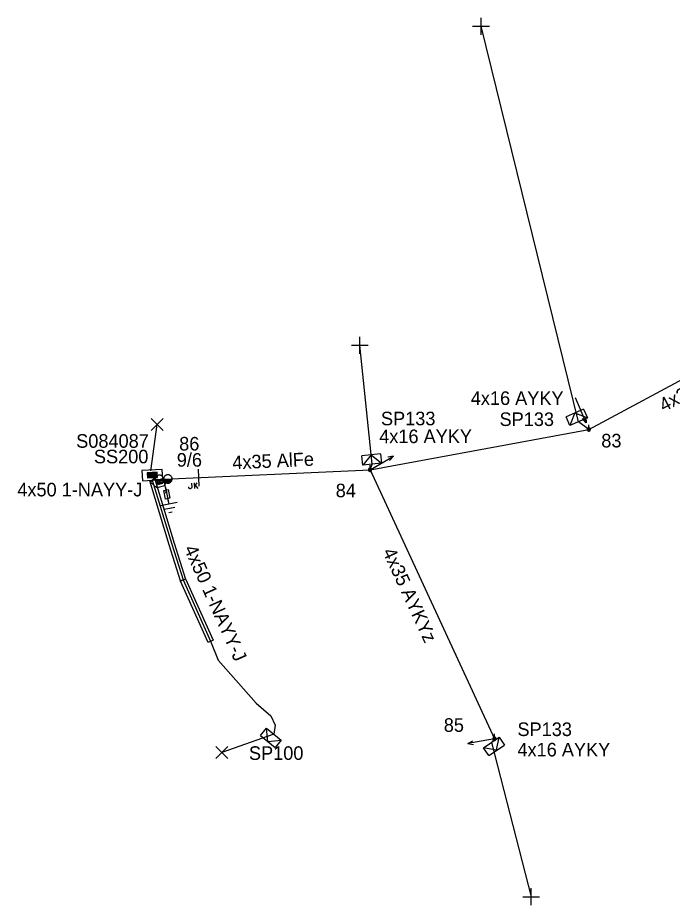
# Model space of a CAD drawing. Extents: x -788458 to -786145, y -1154772 to -1152372.
# Drawn here: x -787276.6 to -787228.3, y -1152553.9 to -1152488.5 of the extents above; entities that cross this region are included whole.
import ezdxf

# ---------------------------------------------------------------- set-up
doc = ezdxf.new("R2010")
doc.units = 0
for name, color, linetype in [('Vrstva 1', 7, 'Continuous'), ('Vrstva 12', 7, 'Continuous'), ('Vrstva 13', 7, 'Continuous'), ('Vrstva 14', 7, 'Continuous'), ('Vrstva 15', 7, 'Continuous'), ('Vrstva 16', 7, 'Continuous'), ('Vrstva 18', 7, 'Continuous'), ('Vrstva 2', 7, 'Continuous'), ('Vrstva 20', 7, 'Continuous'), ('Vrstva 28', 7, 'Continuous'), ('Vrstva 29', 7, 'Continuous'), ('Vrstva 30', 7, 'Continuous'), ('Vrstva 31', 7, 'Continuous'), ('Vrstva 33', 7, 'Continuous'), ('Vrstva 34', 7, 'Continuous'), ('Vrstva 5', 7, 'Continuous'), ('Vrstva 52', 7, 'Continuous'), ('Vrstva 53', 7, 'Continuous'), ('Vrstva 54', 7, 'Continuous'), ('Vrstva 59', 7, 'Continuous'), ('Vrstva 6', 7, 'Continuous'), ('Vrstva 8', 7, 'Continuous'), ('Vrstva 9', 7, 'Continuous')]:
    doc.layers.add(name, color=color, linetype=linetype)

# ---------------------------------------------------------------- blocks, each defined once
blk = doc.blocks.new('NN450')
at = {"layer": 'Vrstva 2'}
for points in [[(0, 0), (0, 0.07), (-0.01, 0.13), (-0.03, 0.19), (-0.05, 0.25), (-0.08, 0.31), (-0.12, 0.37), (-0.16, 0.42), (-0.21, 0.46), (-0.26, 0.51), (-0.31, 0.54), (-0.37, 0.57), (-0.43, 0.59), (-0.5, 0.61), (-0.56, 0.62), (-0.63, 0.62), (-0.69, 0.62), (-0.75, 0.61), (-0.82, 0.59), (-0.88, 0.57), (-0.94, 0.54), (-0.99, 0.51), (-1.04, 0.46), (-1.09, 0.42), (-1.13, 0.37), (-1.17, 0.31), (-1.2, 0.25), (-1.22, 0.19), (-1.24, 0.13), (-1.25, 0.07), (-1.25, 0), (-1.25, -0.07), (-1.24, -0.13), (-1.22, -0.19), (-1.2, -0.25), (-1.17, -0.31), (-1.13, -0.37), (-1.09, -0.42), (-1.04, -0.46), (-0.99, -0.51), (-0.94, -0.54), (-0.88, -0.57), (-0.82, -0.59), (-0.75, -0.61), (-0.69, -0.62), (-0.62, -0.63), (-0.56, -0.62), (-0.5, -0.61), (-0.43, -0.59), (-0.37, -0.57), (-0.31, -0.54), (-0.26, -0.51), (-0.21, -0.46), (-0.16, -0.42), (-0.12, -0.37), (-0.08, -0.31), (-0.05, -0.25), (-0.03, -0.19), (-0.01, -0.13), (0, -0.07), (0, 0)], [(1.25, 0), (1.25, 0.07), (1.24, 0.13), (1.22, 0.19), (1.2, 0.25), (1.17, 0.31), (1.13, 0.37), (1.09, 0.42), (1.04, 0.46), (0.99, 0.51), (0.94, 0.54), (0.88, 0.57), (0.82, 0.59), (0.75, 0.61), (0.69, 0.62), (0.62, 0.62), (0.56, 0.62), (0.5, 0.61), (0.43, 0.59), (0.37, 0.57), (0.31, 0.54), (0.26, 0.51), (0.21, 0.46), (0.16, 0.42), (0.12, 0.37), (0.08, 0.31), (0.05, 0.25), (0.03, 0.19), (0.01, 0.13), (0, 0.07), (0, 0), (0, -0.07), (0.01, -0.13), (0.03, -0.19), (0.05, -0.25), (0.08, -0.31), (0.12, -0.37), (0.16, -0.42), (0.21, -0.46), (0.26, -0.51), (0.31, -0.54), (0.37, -0.57), (0.43, -0.59), (0.5, -0.61), (0.56, -0.62), (0.63, -0.63), (0.69, -0.62), (0.75, -0.61), (0.82, -0.59), (0.88, -0.57), (0.94, -0.54), (0.99, -0.51), (1.04, -0.46), (1.09, -0.42), (1.13, -0.37), (1.17, -0.31), (1.2, -0.25), (1.22, -0.19), (1.24, -0.13), (1.25, -0.07), (1.25, 0)], [(-1.25, 0), (1.25, 0)], [(-1.23, -0.16), (-0.02, -0.16)], [(-1.16, -0.32), (-0.09, -0.32)], [(-1.03, -0.47), (-0.22, -0.47)], [(0.02, -0.16), (1.23, -0.16)], [(0.09, -0.32), (1.16, -0.32)], [(0.22, -0.47), (1.03, -0.47)]]:
    blk.add_lwpolyline(points, dxfattribs=at)
blk = doc.blocks.new('NN560')
at = {"layer": 'Vrstva 2'}
for points in [[(1.999, -0.001), (1.59, 0.141)], [(0, -0.001), (1.999, -0.001)], [(1.999, -0.001), (1.59, -0.134)]]:
    blk.add_lwpolyline(points, dxfattribs=at)
blk = doc.blocks.new('NN840')
at = {"layer": 'Vrstva 15'}
for points in [[(0.003, 0.619), (0.003, -0.631)], [(-0.538, -0.385), (-0.538, -0.71)], [(-0.332, -0.385), (-0.332, -0.798)], [(-0.332, -0.641), (-0.125, -0.385)], [(-0.263, -0.557), (-0.091, -0.798)], [(-0.745, -0.71), (-0.745, -0.66)], [(-0.73, -0.764), (-0.745, -0.71)], [(-0.657, -0.798), (-0.73, -0.764)], [(-0.627, -0.798), (-0.657, -0.798)], [(-0.558, -0.764), (-0.627, -0.798)], [(-0.538, -0.71), (-0.558, -0.764)]]:
    blk.add_lwpolyline(points, dxfattribs=at)
blk = doc.blocks.new('NN565')
at = {"layer": 'Vrstva 2'}
for points in [[(0.015, 0.528), (0.015, 2.528)], [(0.157, 0.937), (0.015, 0.528), (-0.119, 0.937)]]:
    blk.add_lwpolyline(points, dxfattribs=at)
blk = doc.blocks.new('NN800')
at = {"layer": 'Vrstva 1'}
for points in [[(-0.442, 0.442), (0.442, -0.442)], [(-0.442, -0.442), (0.442, 0.442)]]:
    blk.add_lwpolyline(points, dxfattribs=at)
blk = doc.blocks.new('NN820')
at = {"layer": 'Vrstva 13'}
for points in [[(-0.003, 0.004), (-0.003, -1.049)], [(-0.165, -0.813), (0.165, -0.813)], [(-0.165, -1.473), (-0.165, -0.813)], [(-0.003, -1.049), (-0.062, -0.926)], [(-0.003, -1.049), (0.057, -0.926)], [(0.165, -0.813), (0.165, -1.473)], [(0.165, -1.473), (-0.165, -1.473)], [(-0.003, -1.473), (-0.003, -1.871)]]:
    blk.add_lwpolyline(points, dxfattribs=at)
blk = doc.blocks.new('NN620')
at = {"layer": 'Vrstva 8'}
for points in [[(0.752, 0.004), (-0.748, 0.004)], [(-0.748, 0.004), (-0.748, -0.746)], [(0.752, -0.746), (0.752, 0.004)], [(0.368, -0.18), (-0.376, -0.18)], [(-0.376, -0.18), (-0.376, -0.558)], [(-0.376, -0.558), (0.368, -0.558)], [(0.321, -0.227), (-0.329, -0.227)], [(-0.329, -0.227), (-0.329, -0.51)], [(-0.329, -0.51), (0.321, -0.51)], [(0.274, -0.274), (-0.281, -0.274)], [(-0.281, -0.274), (-0.281, -0.463)], [(-0.281, -0.463), (0.274, -0.463)], [(0.227, -0.321), (-0.234, -0.321)], [(-0.234, -0.321), (-0.234, -0.416)], [(-0.234, -0.416), (0.227, -0.416)], [(-0.193, -0.369), (0.185, -0.369)], [(0.227, -0.416), (0.227, -0.321)], [(0.274, -0.463), (0.274, -0.274)], [(0.321, -0.51), (0.321, -0.227)], [(0.368, -0.558), (0.368, -0.18)], [(-0.748, -0.746), (0.752, -0.746)]]:
    blk.add_lwpolyline(points, dxfattribs=at)
blk = doc.blocks.new('NN630')
at = {"layer": 'Vrstva 9'}
for points in [[(-0.003, -0.7), (-0.703, 0)], [(-0.703, -0.7), (-0.703, 0), (0.697, 0), (0.697, -0.7)], [(-0.003, -0.7), (0.697, 0)], [(-0.703, -0.7), (0.697, -0.7)]]:
    blk.add_lwpolyline(points, dxfattribs=at)
blk = doc.blocks.new('NN810')
at = {"layer": 'Vrstva 14'}
for points in [[(0.004, -0.64), (0.004, -1.89)], [(0.629, -1.89), (-0.621, -1.89)], [(0.388, -2.2), (-0.399, -2.2)], [(0.004, -2.515), (-0.124, -2.515)], [(0.137, -2.515), (0.004, -2.515)]]:
    blk.add_lwpolyline(points, dxfattribs=at)
blk = doc.blocks.new('NN500')
at = {"layer": 'Vrstva 2'}
for points in [[(0, -0.24), (0.02, -0.23), (0.05, -0.23), (0.07, -0.22), (0.09, -0.22), (0.12, -0.2), (0.14, -0.19), (0.16, -0.18), (0.17, -0.16), (0.19, -0.14), (0.2, -0.12), (0.21, -0.1), (0.22, -0.07), (0.23, -0.05), (0.23, -0.02), (0.23, 0), (0.23, 0.02), (0.23, 0.05), (0.22, 0.07), (0.21, 0.1), (0.2, 0.12), (0.19, 0.14), (0.17, 0.16), (0.16, 0.17), (0.14, 0.19), (0.12, 0.2), (0.09, 0.21), (0.07, 0.22), (0.05, 0.23), (0.02, 0.23), (0, 0.23), (-0.03, 0.23), (-0.05, 0.23), (-0.07, 0.22), (-0.1, 0.21), (-0.12, 0.2), (-0.14, 0.19), (-0.16, 0.17), (-0.18, 0.16), (-0.19, 0.14), (-0.2, 0.12), (-0.22, 0.1), (-0.22, 0.07), (-0.23, 0.05), (-0.23, 0.02), (-0.24, 0), (-0.23, -0.02), (-0.23, -0.05), (-0.22, -0.07), (-0.22, -0.1), (-0.2, -0.12), (-0.19, -0.14), (-0.18, -0.16), (-0.16, -0.18), (-0.14, -0.19), (-0.12, -0.2), (-0.1, -0.22), (-0.07, -0.22), (-0.05, -0.23), (-0.03, -0.23), (0, -0.24)], [(0, -0.24), (0.02, -0.23), (0.05, -0.23), (0.07, -0.22), (0.09, -0.22), (0.12, -0.2), (0.14, -0.19), (0.16, -0.18), (0.17, -0.16), (0.19, -0.14), (0.2, -0.12), (0.21, -0.1), (0.22, -0.07), (0.23, -0.05), (0.23, -0.02), (0.23, 0), (0.23, 0.02), (0.23, 0.05), (0.22, 0.07), (0.21, 0.1), (0.2, 0.12), (0.19, 0.14), (0.17, 0.16), (0.16, 0.17), (0.14, 0.19), (0.12, 0.2), (0.09, 0.21), (0.07, 0.22), (0.05, 0.23), (0.02, 0.23), (0, 0.23), (-0.03, 0.23), (-0.05, 0.23), (-0.07, 0.22), (-0.1, 0.21), (-0.12, 0.2), (-0.14, 0.19), (-0.16, 0.17), (-0.18, 0.16), (-0.19, 0.14), (-0.2, 0.12), (-0.22, 0.1), (-0.22, 0.07), (-0.23, 0.05), (-0.23, 0.02), (-0.24, 0), (-0.23, -0.02), (-0.23, -0.05), (-0.22, -0.07), (-0.22, -0.1), (-0.2, -0.12), (-0.19, -0.14), (-0.18, -0.16), (-0.16, -0.18), (-0.14, -0.19), (-0.12, -0.2), (-0.1, -0.22), (-0.07, -0.22), (-0.05, -0.23), (-0.03, -0.23), (0, -0.24)], [(0, -0.21), (0.02, -0.2), (0.04, -0.2), (0.06, -0.2), (0.08, -0.19), (0.1, -0.18), (0.12, -0.17), (0.14, -0.15), (0.15, -0.14), (0.16, -0.12), (0.18, -0.1), (0.19, -0.08), (0.19, -0.06), (0.2, -0.04), (0.2, -0.02), (0.2, 0), (0.2, 0.02), (0.2, 0.04), (0.19, 0.06), (0.19, 0.08), (0.18, 0.1), (0.16, 0.12), (0.15, 0.14), (0.14, 0.15), (0.12, 0.17), (0.1, 0.18), (0.08, 0.19), (0.06, 0.19), (0.04, 0.2), (0.02, 0.2), (0, 0.2), (-0.02, 0.2), (-0.04, 0.2), (-0.06, 0.19), (-0.08, 0.19), (-0.1, 0.18), (-0.12, 0.17), (-0.14, 0.15), (-0.15, 0.14), (-0.17, 0.12), (-0.18, 0.1), (-0.19, 0.08), (-0.2, 0.06), (-0.2, 0.04), (-0.21, 0.02), (-0.21, 0), (-0.21, -0.02), (-0.2, -0.04), (-0.2, -0.06), (-0.19, -0.08), (-0.18, -0.1), (-0.17, -0.12), (-0.15, -0.14), (-0.14, -0.15), (-0.12, -0.17), (-0.1, -0.18), (-0.08, -0.19), (-0.06, -0.2), (-0.04, -0.2), (-0.02, -0.2), (0, -0.21)], [(0, -0.18), (0.02, -0.18), (0.04, -0.17), (0.05, -0.17), (0.07, -0.16), (0.09, -0.15), (0.1, -0.14), (0.12, -0.13), (0.13, -0.12), (0.14, -0.1), (0.15, -0.09), (0.16, -0.07), (0.17, -0.05), (0.17, -0.04), (0.17, -0.02), (0.17, 0), (0.17, 0.02), (0.17, 0.04), (0.17, 0.05), (0.16, 0.07), (0.15, 0.09), (0.14, 0.1), (0.13, 0.12), (0.12, 0.13), (0.1, 0.14), (0.09, 0.15), (0.07, 0.16), (0.05, 0.17), (0.04, 0.17), (0.02, 0.17), (0, 0.18), (-0.02, 0.17), (-0.04, 0.17), (-0.06, 0.17), (-0.07, 0.16), (-0.09, 0.15), (-0.1, 0.14), (-0.12, 0.13), (-0.13, 0.12), (-0.14, 0.1), (-0.15, 0.09), (-0.16, 0.07), (-0.17, 0.05), (-0.17, 0.04), (-0.18, 0.02), (-0.18, 0), (-0.18, -0.02), (-0.17, -0.04), (-0.17, -0.05), (-0.16, -0.07), (-0.15, -0.09), (-0.14, -0.1), (-0.13, -0.12), (-0.12, -0.13), (-0.1, -0.14), (-0.09, -0.15), (-0.07, -0.16), (-0.06, -0.17), (-0.04, -0.17), (-0.02, -0.18), (0, -0.18)], [(0, -0.15), (0.01, -0.15), (0.03, -0.14), (0.04, -0.14), (0.06, -0.13), (0.07, -0.13), (0.08, -0.12), (0.1, -0.11), (0.11, -0.1), (0.12, -0.09), (0.13, -0.07), (0.13, -0.06), (0.14, -0.05), (0.14, -0.03), (0.14, -0.02), (0.14, 0), (0.14, 0.01), (0.14, 0.03), (0.14, 0.04), (0.13, 0.06), (0.13, 0.07), (0.12, 0.09), (0.11, 0.1), (0.1, 0.11), (0.08, 0.12), (0.07, 0.13), (0.06, 0.13), (0.04, 0.14), (0.03, 0.14), (0.01, 0.14), (0, 0.15), (-0.02, 0.14), (-0.03, 0.14), (-0.05, 0.14), (-0.06, 0.13), (-0.07, 0.13), (-0.09, 0.12), (-0.1, 0.11), (-0.11, 0.1), (-0.12, 0.09), (-0.13, 0.07), (-0.13, 0.06), (-0.14, 0.04), (-0.14, 0.03), (-0.15, 0.01), (-0.15, 0), (-0.15, -0.02), (-0.14, -0.03), (-0.14, -0.05), (-0.13, -0.06), (-0.13, -0.07), (-0.12, -0.09), (-0.11, -0.1), (-0.1, -0.11), (-0.09, -0.12), (-0.07, -0.13), (-0.06, -0.13), (-0.05, -0.14), (-0.03, -0.14), (-0.02, -0.15), (0, -0.15)], [(0, -0.12), (0.01, -0.12), (0.02, -0.11), (0.03, -0.11), (0.05, -0.11), (0.06, -0.1), (0.07, -0.09), (0.08, -0.09), (0.09, -0.08), (0.09, -0.07), (0.1, -0.06), (0.11, -0.05), (0.11, -0.04), (0.11, -0.02), (0.11, -0.01), (0.12, 0), (0.11, 0.01), (0.11, 0.02), (0.11, 0.04), (0.11, 0.05), (0.1, 0.06), (0.09, 0.07), (0.09, 0.08), (0.08, 0.09), (0.07, 0.09), (0.06, 0.1), (0.05, 0.11), (0.03, 0.11), (0.02, 0.11), (0.01, 0.12), (0, 0.12), (-0.01, 0.12), (-0.03, 0.11), (-0.04, 0.11), (-0.05, 0.11), (-0.06, 0.1), (-0.07, 0.09), (-0.08, 0.09), (-0.09, 0.08), (-0.1, 0.07), (-0.1, 0.06), (-0.11, 0.05), (-0.11, 0.04), (-0.12, 0.02), (-0.12, 0.01), (-0.12, 0), (-0.12, -0.01), (-0.12, -0.02), (-0.11, -0.04), (-0.11, -0.05), (-0.1, -0.06), (-0.1, -0.07), (-0.09, -0.08), (-0.08, -0.09), (-0.07, -0.09), (-0.06, -0.1), (-0.05, -0.11), (-0.04, -0.11), (-0.03, -0.11), (-0.01, -0.12), (0, -0.12)], [(0, -0.09), (0.01, -0.09), (0.02, -0.09), (0.03, -0.08), (0.03, -0.08), (0.04, -0.08), (0.05, -0.07), (0.06, -0.07), (0.06, -0.06), (0.07, -0.05), (0.07, -0.04), (0.08, -0.04), (0.08, -0.03), (0.08, -0.02), (0.09, -0.01), (0.09, 0), (0.09, 0.01), (0.08, 0.02), (0.08, 0.03), (0.08, 0.03), (0.07, 0.04), (0.07, 0.05), (0.06, 0.06), (0.06, 0.06), (0.05, 0.07), (0.04, 0.07), (0.03, 0.08), (0.03, 0.08), (0.02, 0.08), (0.01, 0.09), (0, 0.09), (-0.01, 0.09), (-0.02, 0.08), (-0.03, 0.08), (-0.04, 0.08), (-0.04, 0.07), (-0.05, 0.07), (-0.06, 0.06), (-0.07, 0.06), (-0.07, 0.05), (-0.08, 0.04), (-0.08, 0.03), (-0.08, 0.03), (-0.09, 0.02), (-0.09, 0.01), (-0.09, 0), (-0.09, -0.01), (-0.09, -0.02), (-0.08, -0.03), (-0.08, -0.04), (-0.08, -0.04), (-0.07, -0.05), (-0.07, -0.06), (-0.06, -0.07), (-0.05, -0.07), (-0.04, -0.08), (-0.04, -0.08), (-0.03, -0.08), (-0.02, -0.09), (-0.01, -0.09), (0, -0.09)], [(0, -0.06), (0, -0.06), (0.01, -0.06), (0.02, -0.05), (0.02, -0.05), (0.03, -0.05), (0.03, -0.05), (0.04, -0.04), (0.04, -0.04), (0.05, -0.03), (0.05, -0.03), (0.05, -0.02), (0.05, -0.02), (0.05, -0.01), (0.06, -0.01), (0.06, 0), (0.06, 0.01), (0.05, 0.01), (0.05, 0.02), (0.05, 0.02), (0.05, 0.03), (0.05, 0.03), (0.04, 0.04), (0.04, 0.04), (0.03, 0.05), (0.03, 0.05), (0.02, 0.05), (0.02, 0.05), (0.01, 0.06), (0, 0.06), (0, 0.06), (-0.01, 0.06), (-0.01, 0.06), (-0.02, 0.05), (-0.02, 0.05), (-0.03, 0.05), (-0.03, 0.05), (-0.04, 0.04), (-0.04, 0.04), (-0.05, 0.03), (-0.05, 0.03), (-0.05, 0.02), (-0.06, 0.02), (-0.06, 0.01), (-0.06, 0.01), (-0.06, 0), (-0.06, -0.01), (-0.06, -0.01), (-0.06, -0.02), (-0.05, -0.02), (-0.05, -0.03), (-0.05, -0.03), (-0.04, -0.04), (-0.04, -0.04), (-0.03, -0.05), (-0.03, -0.05), (-0.02, -0.05), (-0.02, -0.05), (-0.01, -0.06), (-0.01, -0.06), (0, -0.06)], [(0, -0.03), (0, -0.03), (0, -0.03), (0.01, -0.03), (0.01, -0.03), (0.01, -0.02), (0.02, -0.02), (0.02, -0.02), (0.02, -0.02), (0.02, -0.02), (0.02, -0.01), (0.02, -0.01), (0.03, -0.01), (0.03, -0.01), (0.03, 0), (0.03, 0), (0.03, 0), (0.03, 0.01), (0.03, 0.01), (0.02, 0.01), (0.02, 0.01), (0.02, 0.02), (0.02, 0.02), (0.02, 0.02), (0.02, 0.02), (0.01, 0.02), (0.01, 0.02), (0.01, 0.03), (0, 0.03), (0, 0.03), (0, 0.03), (0, 0.03), (-0.01, 0.03), (-0.01, 0.03), (-0.01, 0.02), (-0.02, 0.02), (-0.02, 0.02), (-0.02, 0.02), (-0.02, 0.02), (-0.02, 0.02), (-0.03, 0.01), (-0.03, 0.01), (-0.03, 0.01), (-0.03, 0.01), (-0.03, 0), (-0.03, 0), (-0.03, 0), (-0.03, -0.01), (-0.03, -0.01), (-0.03, -0.01), (-0.03, -0.01), (-0.02, -0.02), (-0.02, -0.02), (-0.02, -0.02), (-0.02, -0.02), (-0.02, -0.02), (-0.01, -0.03), (-0.01, -0.03), (-0.01, -0.03), (0, -0.03), (0, -0.03)], [(0.23, 0), (0.7, 0)]]:
    blk.add_lwpolyline(points, dxfattribs=at)

msp = doc.modelspace()

# ---------------------------------------------------------------- linework, layer by layer
at = {"layer": 'Vrstva 1'}
for points in [[(-787250.63, -1152521.8), (-787234.5, -1152518.83), (-787219.59, -1152510.84), (-787199.57, -1152504.09)], [(-787265.84, -1152522.49), (-787250.63, -1152521.8)]]:
    msp.add_lwpolyline(points, dxfattribs=at)
at = {"layer": 'Vrstva 20'}
for points in [[(-787266.489, -1152522.502), (-787265.059, -1152527.211), (-787264.219, -1152529.849), (-787264.601, -1152529.971), (-787265.441, -1152527.329), (-787266.871, -1152522.618)], [(-787266.547, -1152522.411), (-787266.245, -1152522.681), (-787266.091, -1152522.643), (-787266.033, -1152522.436), (-787265.647, -1152522.544), (-787265.769, -1152522.977), (-787266.355, -1152523.119), (-787266.813, -1152522.709)], [(-787264.228, -1152529.828), (-787262.198, -1152534.348), (-787262.562, -1152534.512), (-787264.592, -1152529.992)]]:
    msp.add_lwpolyline(points, close=True, dxfattribs=at)
at = {"layer": 'Vrstva 5'}
for points in [[(-787266.68, -1152522.56), (-787265.25, -1152527.27), (-787264.41, -1152529.91), (-787262.38, -1152534.43), (-787261.83, -1152535.83), (-787259.01, -1152539), (-787257.94, -1152539.92), (-787257.62, -1152540.61), (-787257.71, -1152541.28)], [(-787265.84, -1152522.49), (-787265.93, -1152522.81), (-787266.3, -1152522.9), (-787266.459, -1152522.546)]]:
    msp.add_lwpolyline(points, dxfattribs=at)
at = {"layer": 'Vrstva 52'}
for points in [[(-787234.5, -1152518.83), (-787235.25, -1152518.26)], [(-787250.63, -1152521.8), (-787250.47, -1152521.39)], [(-787250.63, -1152521.8), (-787241.46, -1152541.61)], [(-787241.46, -1152541.61), (-787241.68, -1152541.88)]]:
    msp.add_lwpolyline(points, dxfattribs=at)
at = {"layer": 'Vrstva 59'}
for points in [[(-787235.25, -1152518.26), (-787242.44, -1152489.13)], [(-787250.47, -1152521.39), (-787251.38, -1152512.63)], [(-787266.791, -1152521.884), (-787266.33, -1152518.466)], [(-787257.71, -1152541.28), (-787261.545, -1152542.614)], [(-787241.68, -1152541.88), (-787238.75, -1152553.25)]]:
    msp.add_lwpolyline(points, dxfattribs=at)

# ---------------------------------------------------------------- block references
at = {"layer": 'Vrstva 13'}
for name, p, rotation in [('NN565', (-787234.5, -1152518.83), 23.033524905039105), ('NN560', (-787250.63, -1152521.8), 30.129041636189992), ('NN560', (-787241.46, -1152541.61), -169.56978056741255)]:
    msp.add_blockref(name, p, dxfattribs=dict(at, rotation=rotation))
at = {"layer": 'Vrstva 13', "xscale": 0.5}
for name, p, yscale, rotation in [('NN500', (-787234.5, -1152518.83), 0.5, 90), ('NN500', (-787250.63, -1152521.8), 0.5, 90), ('NN450', (-787265.84, -1152522.49), 0.49999999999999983, 2.59745706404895), ('NN500', (-787241.46, -1152541.61), 0.5, 90)]:
    msp.add_blockref(name, p, dxfattribs=dict(at, yscale=yscale, rotation=rotation))
at = {"layer": 'Vrstva 15', "rotation": 11.49696682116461}
msp.add_blockref('NN810', (-787265.84, -1152522.49), dxfattribs=at)
at = {"layer": 'Vrstva 16', "rotation": 11.596982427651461}
msp.add_blockref('NN820', (-787265.84, -1152522.49), dxfattribs=at)
at = {"layer": 'Vrstva 18', "rotation": 2.597366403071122}
msp.add_blockref('NN840', (-787263.269, -1152522.373), dxfattribs=at)
at = {"layer": 'Vrstva 28', "rotation": -176.63352909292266}
msp.add_blockref('NN620', (-787266.661, -1152522.559), dxfattribs=at)
at = {"layer": 'Vrstva 31'}
for p, rotation in [((-787235.25, -1152518.26), -156.48203836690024), ((-787250.47, -1152521.39), -173.49437345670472), ((-787257.71, -1152541.28), -39.50087906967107), ((-787241.68, -1152541.88), 33.690067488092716)]:
    msp.add_blockref('NN630', p, dxfattribs=dict(at, rotation=rotation))
at = {"layer": 'Vrstva 34'}
for p, rotation in [((-787242.44, -1152489.13), 44.99999995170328), ((-787251.38, -1152512.63), 45), ((-787238.75, -1152553.25), 45)]:
    msp.add_blockref('NN800', p, dxfattribs=dict(at, rotation=rotation))
for p in [(-787266.33, -1152518.466), (-787261.545, -1152542.614)]:
    msp.add_blockref('NN800', p, dxfattribs=at)

# ---------------------------------------------------------------- texts
at = {"layer": 'Vrstva 12'}
msp.add_text('9/6', height=1, dxfattribs=at).set_placement((-787264.874, -1152521.57))
at = {"layer": 'Vrstva 14'}
for s, p in [('86', (-787264.696, -1152520.381)), ('83', (-787233.581, -1152520.153)), ('84', (-787253.159, -1152523.825)), ('85', (-787245.193, -1152541.102))]:
    msp.add_text(s, height=1, dxfattribs=at).set_placement(p)
at = {"layer": 'Vrstva 2'}
for rotation, p in [(28.186, (-787228.973, -1152517.559)), (2.609, (-787260.757, -1152521.772))]:
    msp.add_text('4x35 AlFe', height=1, rotation=rotation, dxfattribs=at).set_placement(p)
at = {"layer": 'Vrstva 29'}
msp.add_text('S084087', height=1, dxfattribs=at).set_placement((-787272.289, -1152520.179))
at = {"layer": 'Vrstva 30'}
msp.add_text('SS200', height=1, dxfattribs=at).set_placement((-787270.982, -1152521.324))
at = {"layer": 'Vrstva 33'}
for s, p in [('SP133', (-787249.823, -1152518.523)), ('SP133', (-787241.081, -1152518.575)), ('SP133', (-787239.762, -1152541.413)), ('SP100', (-787259.554, -1152543.168))]:
    msp.add_text(s, height=1, dxfattribs=at).set_placement(p)
at = {"layer": 'Vrstva 53'}
msp.add_text('4x35 AYKYz', height=1, rotation=294.839, dxfattribs=at).set_placement((-787249.733, -1152527.829))
at = {"layer": 'Vrstva 54'}
msp.add_text('4x16 AYKY', height=1, dxfattribs=at).set_placement((-787243.202, -1152517.023))
for rotation, p in [(0.16, (-787249.951, -1152519.842)), (359.978, (-787239.762, -1152542.913))]:
    msp.add_text('4x16 AYKY', height=1, rotation=rotation, dxfattribs=at).set_placement(p)
at = {"layer": 'Vrstva 6'}
msp.add_text('4x50 1-NAYY-J', height=1, dxfattribs=at).set_placement((-787276.628, -1152523.761))
msp.add_text('4x50 1-NAYY-J', height=1, rotation=294.186, dxfattribs=at).set_placement((-787264.363, -1152527.61))

doc.saveas('drawing.dxf')
